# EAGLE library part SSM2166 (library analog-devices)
Microphone Preamplifier with Variable Compression and Noise Gating Source: http://www.analog.com/static/imported-files/data_sheets/SSM2166.pdf
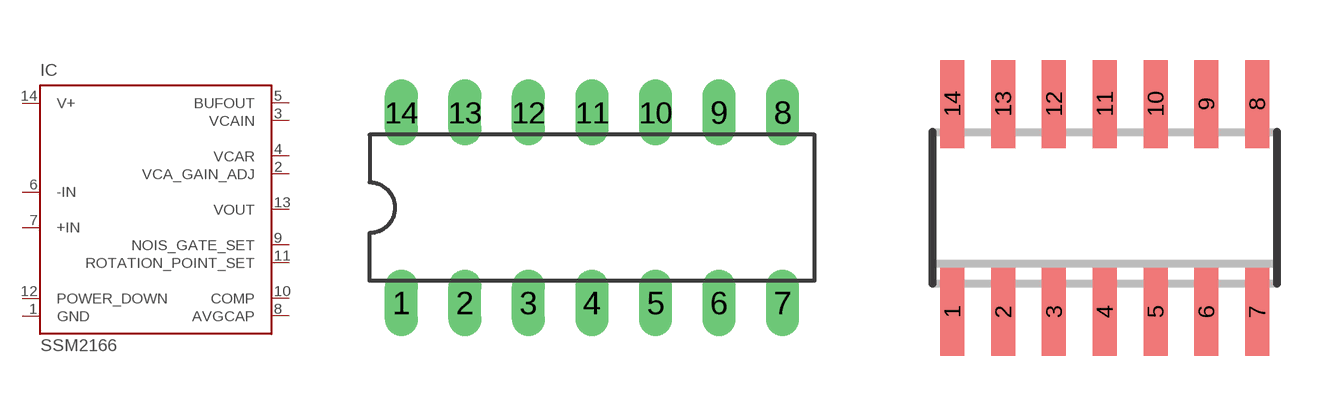
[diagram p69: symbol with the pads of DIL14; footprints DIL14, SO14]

Designator prefix IC

## SSM2166P (OC_FARNELL: unknown; OC_NEWARK: unknown)  [DIL14]
1  GND  pwr
2  VCA_GAIN_ADJ  in
3  VCAIN  in
4  VCAR  in
5  BUFOUT  out
6  -IN  in
7  +IN  in
8  AVGCAP  pas
9  NOIS_GATE_SET  pas
10  COMP  pas
11  ROTATION_POINT_SET  pas
12  POWER_DOWN  in
13  VOUT  out
14  V+  pwr

## SSM2166S (MF: ALTERA CORPORATION; MPN: SSM2166S-REEL; OC_FARNELL: 1424669; OC_NEWARK: 13B4818)  [SO14]
Pads as for DIL14

## Footprint DIL14 (pad centres in mm)
Dual In Line Package
drill 0.813 long: 1 -7.62,-3.81; 2 -5.08,-3.81; 3 -2.54,-3.81; 4 0,-3.81; 5 2.54,-3.81; 6 5.08,-3.81; 7 7.62,-3.81; 8 7.62,3.81; 9 5.08,3.81; 10 2.54,3.81; 11 0,3.81; 12 -2.54,3.81; 13 -5.08,3.81; 14 -7.62,3.81

## Footprint SO14 (pad centres in mm)
14-Lead Narrow-Body SOIC (SO-14) Source: http://www.analog.com/static/imported-files/data_sheets/SSM2166.pdf
smd 0.6 x 2.2: 1 -3.81,-2.6; 2 -2.54,-2.6; 3 -1.27,-2.6; 4 0,-2.6; 5 1.27,-2.6; 6 2.54,-2.6; 7 3.81,-2.6; 8 3.81,2.6; 9 2.54,2.6; 10 1.27,2.6; 11 0,2.6; 12 -1.27,2.6; 13 -2.54,2.6; 14 -3.81,2.6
